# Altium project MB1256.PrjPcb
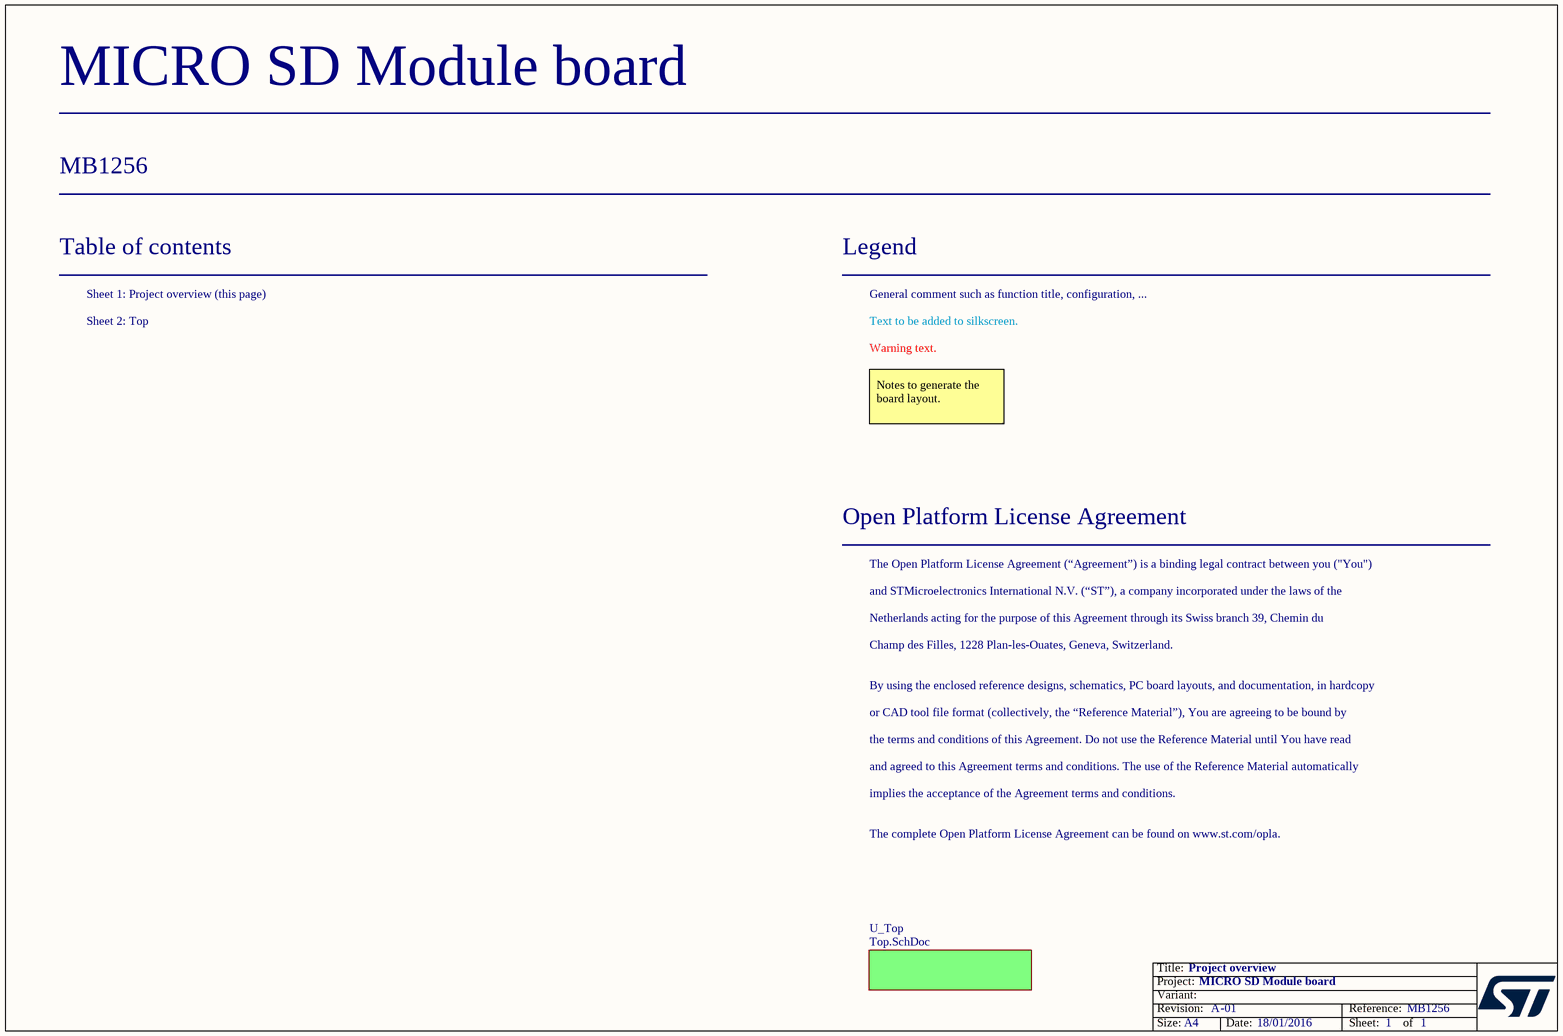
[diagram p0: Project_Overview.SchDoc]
Board_Reference: MB1256; Board_PCB_Revision: A; Board_Name: MICRO SD Module board; Board_Document_Date: 18/01/2016; Board_Assembly_Revision: 01
2 sheets, 5 parts. Net scope: global (net labels, ports and power ports of the same name join across sheets).
Sheets:
  Project_Overview.SchDoc
    U_Top = Top.SchDoc

## Sheet Project_Overview.SchDoc: Project overview
size A4; Date: Not used; ApprovedBy: Not used; CheckedBy: Not used; Author: Not used; CompanyName: STMicroelectronics; DrawnBy: Not used; Engineer: Not used; Organization: Not used; Address1: Not used; Address2: Not used; Address3: Not used; Address4: Not used; DocumentNumber: Not used; Revision: Not used; SheetNumber: 1; SheetTotal: 1

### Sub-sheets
U_Top = Top.SchDoc: no entries

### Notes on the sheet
- Table of contents
- Sheet 1: Project overview (this page)
- Legend
- General comment such as function title, configuration, ...
- Sheet 2: Top
- Text to be added to silkscreen.
- Warning text.
- Notes to generate the board layout.
- Open Platform License Agreement
- The Open Platform License Agreement (“Agreement”) is a binding legal contract between you ("You")
- and STMicroelectronics International N.V. (“ST”), a company incorporated under the laws of the
- Netherlands acting for the purpose of this Agreement through its Swiss branch 39, Chemin du
- Champ des Filles, 1228 Plan-les-Ouates, Geneva, Switzerland.
- By using the enclosed reference designs, schematics, PC board layouts, and documentation, in hardcopy
- or CAD tool file format (collectively, the “Reference Material”), You are agreeing to be bound by
- the terms and conditions of this Agreement. Do not use the Reference Material until You have read
- and agreed to this Agreement terms and conditions. The use of the Reference Material automatically
- implies the acceptance of the Agreement terms and conditions.
- The complete Open Platform License Agreement can be found on www.st.com/opla.

## Sheet Top.SchDoc: Top
size A4; DocumentNumber: MB1256; Revision: A.1; SheetNumber: 1; SheetTotal: 1; Project: STM32H7-EVAL
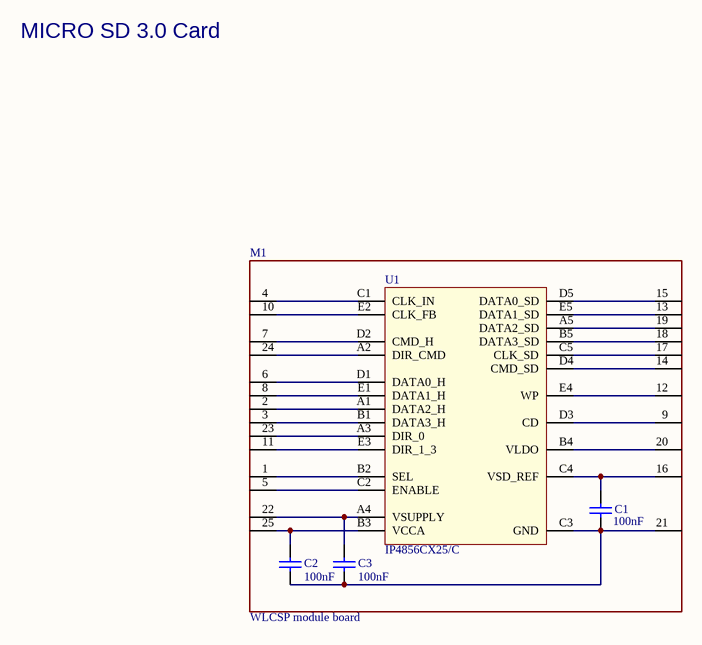
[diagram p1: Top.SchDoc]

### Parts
C1  100nF  [0402C]
C2  100nF  [0402C]
C3  100nF  [0402C]
M1  WLCSP module board  [WLCSP25_0R4_2R05X2R05_module]
U1  IP4856CX25/C  [WLCSP25_0R4_2R05X2R05]

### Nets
NetC1_1: C1.1 M1.16(DATA1_SD) U1.C4(VSD_REF)
NetC1_2: C1.2 C2.2 C3.2 M1.21(WP) U1.C3(GND)
NetC2_1: C2.1 M1.25(GND) U1.B3(VCCA)
NetC3_1: C3.1 M1.22(CD) U1.A4(VSUPPLY)
NetM1_1: M1.1(CLK_IN) U1.B2(SEL)
NetM1_2: M1.2(CLK_FB) U1.A1(DATA2_H)
NetM1_3: M1.3(CMD_H) U1.B1(DATA3_H)
NetM1_4: M1.4(DIR_CMD) U1.C1(CLK_IN)
NetM1_5: M1.5(DATA0_H) U1.C2(ENABLE)
NetM1_6: M1.6(DATA1_H) U1.D1(DATA0_H)
NetM1_7: M1.7(DATA2_H) U1.D2(CMD_H)
NetM1_8: M1.8(DATA3_H) U1.E1(DATA1_H)
NetM1_9: M1.9(DIR_0) U1.D3(CD)
NetM1_10: M1.10(DIR_1_3) U1.E2(CLK_FB)
NetM1_11: M1.11(SEL) U1.E3(DIR_1_3)
NetM1_12: M1.12(ENABLE) U1.E4(WP)
NetM1_13: M1.13(VSUPPLY) U1.E5(DATA1_SD)
NetM1_14: M1.14(VCCA) U1.D4(CMD_SD)
NetM1_15: M1.15(DATA0_SD) U1.D5(DATA0_SD)
NetM1_17: M1.17(DATA2_SD) U1.C5(CLK_SD)
NetM1_18: M1.18(DATA3_SD) U1.B5(DATA3_SD)
NetM1_19: M1.19(CLK_SD) U1.A5(DATA2_SD)
NetM1_20: M1.20(CMD_SD) U1.B4(VLDO)
NetM1_23: M1.23(VLDO) U1.A3(DIR_0)
NetM1_24: M1.24(VSD_REF) U1.A2(DIR_CMD)

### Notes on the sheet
- MICRO SD 3.0 Card

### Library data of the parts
C1-C3 = Cap: Capacitor; Value: 10nF
M1 = WLCSP module board: ECCN_US/EU: 3A991
U1 = IP4856CX25/C: SDcard3.0 dual voltage level  translator; ECCN_US/EU: 3A991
